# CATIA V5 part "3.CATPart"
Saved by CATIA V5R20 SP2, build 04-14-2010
Part number: 3
Bounding box of the stored display mesh (mm): x 92.388 to 150, y -57.403 to 57.403, z -50 to 50
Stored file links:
  C:\Users\Orange\Desktop\Assembly Design-7\3.CATPart
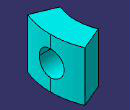
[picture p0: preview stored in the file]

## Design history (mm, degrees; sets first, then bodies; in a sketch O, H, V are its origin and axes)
Body1 (main body)
  Sketch1 on xy-plane, origin (0, 0, 0), H (1, 0, 0), V (0, 1, 0)
    circle A1 centre (0, 0) radius 150
    circle A2 centre (0, 0) radius 100
  Pad1: profile Sketch1, direction (0, 0, 1), length 50, mirrored extent
  Sketch2 on xy-plane, origin (0, 0, 0), H (1, 0, 0), V (0, 1, 0)
    line L1 (0, 0) -> (248.3258, 102.8599)
    point P3 (0, 0)
    line L2 (0, 0) -> (248.3258, -102.8599)
    line L3 (248.3258, -102.8599) -> (212.7952, -288.0728)
    line L4 (212.7952, -288.0728) -> (-253.3585, -220.6889)
    line L5 (-253.3585, -220.6889) -> (-314.1612, 96.0157)
    line L6 (-314.1612, 96.0157) -> (-49.3318, 236.1743)
    line L7 (-49.3318, 236.1743) -> (248.3258, 102.8599)
    coincidence: O P3
  Pocket1: profile Sketch2, direction (0, 0, -1), length 100, mirrored extent
  Sketch3 on yz-plane, origin (0, 0, 0), H (0, 1, 0), V (0, 0, 1)
    circle A1 centre (0, 0) radius 25
  Pocket2: profile Sketch3, direction (1, 0, 0), length 1100
  Sketch4 on zx-plane, origin (0, 0, 0), H (-1, 0, 0), V (0, 0, 1)
    intersected line E1 through (0, 0) direction (-1, 0) from axis of face of Pocket2 from Sketch3.A1
  Sketch5 on zx-plane, origin (0, 0, 0), H (-1, 0, 0), V (0, 0, 1)
    intersected line E1 through (0, 0) direction (-1, 0) from axis of face of Pocket2 from Sketch3.A1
